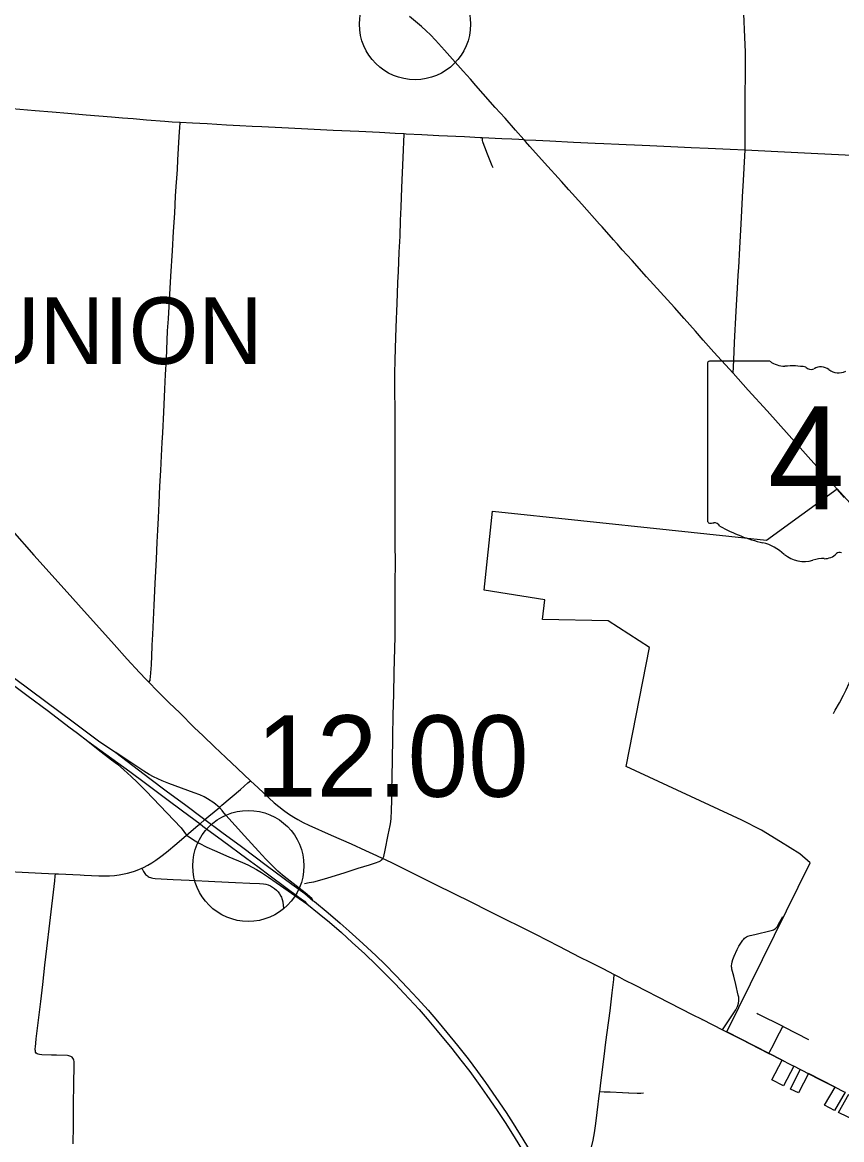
# Model space of a CAD drawing. Extents: x 1597222 to 1925846, y 496284 to 911751.
# Drawn here: x 1687501 to 1698562, y 561679 to 576766 of the extents above; entities that cross this region are included whole.
import ezdxf

# ---------------------------------------------------------------- set-up
doc = ezdxf.new("R2010")
doc.units = 0
for name, color, linetype in [('Default', 7, 'Continuous'), ('GM_X_City_Street', 7, 'Continuous'), ('GM_X_Corporation', 7, 'Continuous'), ('GM_X_County_Road', 7, 'Continuous'), ('GM_X_Interchange_Ramps', 7, 'Continuous'), ('GM_X_State_Route', 7, 'Continuous'), ('GM_X_State_Shield', 7, 'Continuous'), ('GM_X_Township_Road', 7, 'Continuous'), ('GM_X_Township_Text', 7, 'Continuous'), ('GM_X_US_Route', 7, 'Continuous')]:
    doc.layers.add(name, color=color, linetype=linetype)

msp = doc.modelspace()

# ---------------------------------------------------------------- linework, layer by layer
at = {"layer": 'Default'}
for centre in [(1692802, 576741), (1692802, 576741), (1690551, 565375), (1690551, 565375)]:
    msp.add_circle(centre, 750, dxfattribs=at)
at = {"layer": 'GM_X_City_Street'}
for points in [[(1698451, 567435), (1698474, 567479), (1698532, 567579), (1698587, 567680), (1698623, 567754), (1698665, 567843), (1698681, 567872), (1698690, 567886)], [(1696955, 563162), (1696971, 563187), (1696998, 563228), (1697042, 563297), (1697116, 563404), (1697133, 563432), (1697148, 563460), (1697154, 563475), (1697160, 563490), (1697168, 563521), (1697173, 563553), (1697174, 563569), (1697174, 563585), (1697172, 563601), (1697166, 563632), (1697132, 563775), (1697104, 563886), (1697086, 563949), (1697080, 563981), (1697078, 563998), (1697076, 564014), (1697076, 564031), (1697078, 564048), (1697084, 564080), (1697094, 564112), (1697112, 564158), (1697153, 564247), (1697175, 564291), (1697201, 564333), (1697229, 564374), (1697239, 564387), (1697251, 564399), (1697264, 564410), (1697279, 564418), (1697294, 564425), (1697326, 564436), (1697390, 564451), (1697612, 564502), (1697628, 564506), (1697643, 564512), (1697656, 564519), (1697669, 564528), (1697679, 564539), (1697689, 564552), (1697706, 564580), (1697767, 564693)], [(1697418, 563386), (1697432, 563379), (1697768, 563209)], [(1697579, 562843), (1697594, 562870), (1697641, 562958), (1697693, 563062), (1697753, 563180), (1697768, 563209)], [(1697768, 563209), (1697782, 563202), (1698116, 563032)], [(1697759, 562752), (1697772, 562746)], [(1697919, 562671), (1698004, 562626)], [(1698258, 562496), (1698332, 562459), (1698472, 562386)]]:
    msp.add_lwpolyline(points, dxfattribs=at)
at = {"layer": 'GM_X_Corporation'}
for points in [[(1698607, 562321), (1698463, 562073), (1698330, 562146), (1698473, 562389), (1698115, 562571), (1697979, 562309), (1697873, 562361), (1698003, 562628), (1697918, 562672), (1697778, 562407), (1697617, 562485), (1697758, 562754), (1697011, 563134), (1698135, 565417), (1697999, 565537), (1697736, 565700), (1697481, 565859), (1697213, 565994), (1695653, 566716), (1695966, 568325), (1695409, 568686), (1694523, 568702), (1694556, 568969), (1693735, 569099), (1693847, 570164), (1696232, 569913), (1697548, 569775), (1698502, 570468), (1698717, 570227)], [(1698985, 561819), (1698519, 562047), (1698660, 562293)]]:
    msp.add_lwpolyline(points, dxfattribs=at)
at = {"layer": 'GM_X_County_Road'}
for points in [[(1697257, 575044), (1697258, 575249), (1697261, 575610), (1697262, 576233), (1697262, 576364), (1697254, 576564), (1697242, 576881), (1697230, 577216), (1697211, 577527), (1697193, 577838), (1697178, 578083), (1697138, 578787), (1697122, 579066), (1697109, 579311), (1697093, 579590), (1697085, 579671), (1697078, 579720), (1697066, 579784), (1697045, 579863), (1696903, 580368), (1696829, 580637), (1696791, 580776)], [(1685437, 575768), (1685632, 575750), (1685975, 575719), (1686302, 575692), (1686629, 575665), (1686923, 575641), (1687364, 575602), (1687675, 575577), (1687903, 575557), (1688116, 575540), (1688361, 575519), (1688704, 575492), (1688851, 575479), (1688998, 575466), (1689178, 575450), (1689423, 575431), (1689521, 575425), (1689630, 575418)], [(1689630, 575418), (1689799, 575408), (1689996, 575399), (1690258, 575384), (1690438, 575374), (1690602, 575366), (1690733, 575359), (1691093, 575343), (1691355, 575329), (1691699, 575312), (1692043, 575295), (1692321, 575282), (1692534, 575269), (1692656, 575264)], [(1692369, 565474), (1692379, 565501), (1692399, 565587), (1692438, 565794), (1692467, 565922), (1692475, 565971), (1692479, 566020), (1692484, 566119), (1692487, 566267), (1692488, 566381), (1692494, 566595), (1692497, 566791), (1692503, 567119), (1692508, 567415), (1692515, 567694), (1692520, 567989), (1692529, 568317), (1692533, 568464), (1692536, 568563), (1692536, 568645), (1692536, 568989), (1692536, 569203), (1692537, 569465), (1692534, 569728), (1692535, 569974), (1692535, 570236), (1692533, 570450), (1692535, 570761), (1692534, 571057), (1692532, 571467), (1692532, 571615), (1692531, 571713), (1692530, 571819), (1692530, 571910), (1692530, 572025), (1692534, 572205), (1692543, 572517), (1692554, 572762), (1692558, 572861), (1692562, 572975), (1692566, 573107), (1692572, 573254), (1692579, 573401), (1692585, 573533), (1692590, 573664), (1692600, 573877), (1692608, 574090), (1692615, 574270), (1692626, 574532), (1692641, 574942), (1692656, 575256), (1692656, 575264)], [(1692656, 575264), (1692682, 575262), (1692895, 575252), (1693124, 575240), (1693468, 575224), (1693681, 575212), (1693709, 575211)], [(1693709, 575211), (1693976, 575200), (1694107, 575192), (1694205, 575187), (1694271, 575183)], [(1694271, 575183), (1694287, 575182), (1694433, 575175), (1694624, 575166), (1694942, 575150), (1695233, 575137)], [(1695233, 575137), (1695351, 575132), (1695554, 575122), (1695651, 575118)], [(1695651, 575118), (1695764, 575113), (1695973, 575104), (1696352, 575087), (1696531, 575077), (1696760, 575066), (1697056, 575053), (1697257, 575044)], [(1697229, 574489), (1697232, 574551), (1697246, 574796), (1697257, 575044)], [(1697257, 575044), (1697698, 575021), (1698239, 574996), (1698519, 574983), (1698697, 574974)], [(1697098, 572027), (1697107, 572204), (1697116, 572442), (1697138, 572868), (1697160, 573260), (1697166, 573354), (1697172, 573456), (1697187, 573717), (1697205, 574044), (1697229, 574489)], [(1685081, 572425), (1685120, 572384), (1685314, 572184), (1685392, 572100), (1685567, 571905), (1685731, 571722), (1685939, 571489), (1686070, 571343), (1686234, 571159), (1686694, 570647), (1686923, 570391), (1687142, 570147), (1687362, 569903), (1687656, 569573), (1687985, 569207), (1688182, 568988), (1688336, 568817), (1688543, 568584), (1688739, 568364), (1688914, 568169), (1689080, 567987), (1689171, 567892), (1689206, 567856)], [(1689206, 567856), (1689321, 567741), (1689484, 567579), (1689625, 567442), (1689822, 567245), (1689940, 567131), (1690094, 566984), (1690249, 566837), (1690405, 566692), (1690579, 566526)], [(1690160, 566165), (1690195, 566195), (1690445, 566408), (1690545, 566495), (1690579, 566526)], [(1690579, 566526), (1690682, 566429), (1690826, 566295), (1690899, 566229), (1690962, 566176), (1691027, 566126), (1691095, 566078), (1691164, 566034), (1691221, 566001), (1691294, 565962), (1691368, 565927), (1691668, 565792), (1691938, 565672), (1692132, 565584), (1692281, 565515), (1692369, 565474)], [(1689717, 565790), (1689871, 565919), (1689899, 565943), (1689966, 566001), (1690020, 566046), (1690160, 566165)], [(1689112, 565345), (1689135, 565355), (1689193, 565385), (1689249, 565418), (1689304, 565453), (1689370, 565501), (1689448, 565562), (1689586, 565678), (1689717, 565790)], [(1684630, 565427), (1684729, 565423), (1685008, 565409), (1685270, 565397), (1685565, 565383), (1685909, 565366), (1686171, 565356), (1686696, 565330), (1687056, 565313), (1687761, 565278), (1687950, 565269)], [(1688282, 565253), (1688334, 565251), (1688531, 565242), (1688613, 565240), (1688678, 565242), (1688743, 565247), (1688808, 565255), (1688873, 565266), (1688920, 565276), (1688968, 565289), (1689014, 565305), (1689075, 565328), (1689112, 565345)], [(1689112, 565345), (1689138, 565302), (1689155, 565274), (1689165, 565261), (1689176, 565250), (1689188, 565239), (1689201, 565230), (1689214, 565223), (1689229, 565217), (1689244, 565212), (1689260, 565208), (1689292, 565203), (1689374, 565199), (1689538, 565192), (1689752, 565183), (1690097, 565166), (1690376, 565153), (1690573, 565144), (1690704, 565138), (1690754, 565133), (1690786, 565127), (1690819, 565118), (1690849, 565105), (1690879, 565089), (1690906, 565070), (1690931, 565048), (1690954, 565024), (1690974, 564997), (1690991, 564968), (1690998, 564953), (1691004, 564937), (1691009, 564922), (1691017, 564889), (1691023, 564840), (1691025, 564807)], [(1692369, 565474), (1692400, 565460), (1692504, 565411), (1692872, 565228), (1693077, 565126), (1693563, 564885), (1693784, 564775), (1694048, 564643), (1694195, 564569), (1694430, 564452), (1694745, 564291)], [(1687950, 565269), (1687990, 565267), (1688282, 565253)], [(1694745, 564291), (1695029, 564145), (1695159, 564079)], [(1695159, 564079), (1695337, 563989), (1695492, 563907)], [(1695295, 562326), (1695310, 562445), (1695356, 562802), (1695380, 562997), (1695397, 563127), (1695435, 563418), (1695464, 563662), (1695485, 563841), (1695492, 563907)], [(1695492, 563907), (1695562, 563873), (1695626, 563839), (1695773, 563766), (1695921, 563690), (1696078, 563609), (1696544, 563370), (1696672, 563306), (1696676, 563303)], [(1696676, 563303), (1696681, 563301), (1696955, 563162)], [(1696955, 563162), (1697072, 563103), (1697203, 563035), (1697579, 562843)], [(1697579, 562843), (1697611, 562827), (1697713, 562775), (1697759, 562752)], [(1697772, 562746), (1697785, 562739), (1697835, 562713), (1697881, 562690), (1697905, 562677), (1697919, 562671)], [(1698004, 562626), (1698258, 562496)], [(1695047, 561154), (1695073, 561218), (1695107, 561311), (1695137, 561404), (1695160, 561482), (1695184, 561577), (1695205, 561673), (1695223, 561770), (1695241, 561899), (1695259, 562046), (1695292, 562306), (1695295, 562326)], [(1695690, 562305), (1695686, 562305), (1695602, 562309), (1695436, 562318), (1695357, 562321), (1695295, 562326)], [(1698472, 562386), (1698587, 562329), (1698608, 562319)], [(1695885, 562306), (1695852, 562302), (1695802, 562301), (1695690, 562305)]]:
    msp.add_lwpolyline(points, dxfattribs=at)
at = {"layer": 'GM_X_Interchange_Ramps'}
for points in [[(1688386, 567060), (1688523, 566949), (1688706, 566809), (1688784, 566748), (1688871, 566673), (1688969, 566584), (1689052, 566505), (1689166, 566387), (1689644, 565888), (1689717, 565790)], [(1690160, 566165), (1690085, 566227), (1689998, 566283), (1689954, 566306), (1689895, 566334), (1689819, 566364), (1689480, 566489), (1689388, 566524), (1689328, 566551), (1689269, 566579), (1689211, 566611), (1689142, 566654), (1688992, 566755), (1688764, 566907)], [(1691429, 564905), (1691408, 564936), (1691319, 565012), (1691075, 565199), (1691012, 565251), (1690950, 565305), (1690892, 565362), (1690788, 565467), (1690688, 565574), (1690501, 565780), (1690248, 566059), (1690206, 566109), (1690196, 566122), (1690160, 566165)], [(1689717, 565790), (1689832, 565712), (1689889, 565681), (1689991, 565630), (1690095, 565582), (1690290, 565499), (1690471, 565423), (1690545, 565390), (1690604, 565360), (1690660, 565328), (1690730, 565285), (1690824, 565221), (1691342, 564863)]]:
    msp.add_lwpolyline(points, dxfattribs=at)
at = {"layer": 'GM_X_State_Route'}
for points in [[(1694295, 575156), (1694277, 575176), (1694271, 575183), (1694158, 575311), (1694017, 575471), (1693886, 575618), (1693723, 575802), (1693624, 575912), (1693549, 575998), (1693450, 576109), (1693309, 576268), (1693200, 576391), (1693079, 576525), (1693011, 576596), (1692952, 576653), (1692891, 576708), (1692727, 576845)], [(1697098, 572027), (1696838, 572314), (1696694, 572475), (1696589, 572594), (1696434, 572768), (1696304, 572914), (1696116, 573123), (1695928, 573329), (1695732, 573549), (1695599, 573696), (1695536, 573769), (1695521, 573786), (1695480, 573831), (1695328, 574003), (1695294, 574039), (1695053, 574310), (1694879, 574505), (1694781, 574615), (1694551, 574870), (1694354, 575091), (1694295, 575156)], [(1698500, 570463), (1698109, 570898), (1698001, 571019), (1697555, 571520), (1697301, 571800), (1697098, 572027)], [(1698602, 570350), (1698500, 570463)]]:
    msp.add_lwpolyline(points, dxfattribs=at)
at = {"layer": 'GM_X_State_Shield'}
for p, q in [((1696752, 572154), (1696752, 570041)), ((1697594, 572191), (1696779, 572191))]:
    msp.add_line(p, q, dxfattribs=at)
for centre, radius, start, end in [((1696783, 572159), 32.3, 98.1301, 188.1301), ((1697789, 572436), 313, 231.6195, 271.1119), ((1697892, 571004), 1123, 80.4867, 94.9883), ((1698147, 572170), 90.3, 219.7921, 297.1024), ((1698280, 571925), 188, 54.4667, 119.1411), ((1698522, 572260), 226, 233.8562, 294.8282), ((1696784, 570036), 32.5, 171.9584, 258.3066), ((1696789, 570253), 248, 267.339, 280.6039), ((1696839, 569919), 89.5, 29.7484, 93.2717), ((1697970, 571818), 2132, 240.4129, 257.1985), ((1697334, 569092), 667, 47.1842, 75.836), ((1698056, 569909), 423, 230.7004, 286.2918), ((1698331, 569750), 226, 268.777, 315.5493), ((1698535, 569546), 63.5, 65.7517, 132.6484), ((1698300, 569178), 348, 85.6951, 111.2099)]:
    msp.add_arc(centre, radius, start, end, dxfattribs=at)
at = {"layer": 'GM_X_Township_Road'}
for points in [[(1689438, 572077), (1689446, 572222), (1689456, 572468), (1689462, 572599), (1689472, 572763), (1689487, 573009), (1689505, 573337), (1689526, 573681), (1689543, 573943), (1689557, 574189), (1689570, 574418), (1689577, 574549), (1689585, 574664), (1689593, 574778), (1689601, 574909), (1689619, 575221), (1689627, 575352), (1689630, 575406), (1689630, 575418)], [(1693855, 574800), (1693842, 574830), (1693782, 574986), (1693746, 575079), (1693724, 575141), (1693719, 575155), (1693715, 575173), (1693714, 575181), (1693712, 575189), (1693709, 575211)], [(1689255, 568355), (1689263, 568501), (1689272, 568697), (1689282, 568894), (1689295, 569189), (1689310, 569517), (1689320, 569747), (1689330, 569911), (1689337, 570075), (1689347, 570273), (1689358, 570501), (1689370, 570714), (1689379, 570911), (1689390, 571091), (1689396, 571222), (1689410, 571501), (1689426, 571812), (1689435, 572009), (1689438, 572077)], [(1689206, 567856), (1689224, 567878), (1689228, 567893), (1689231, 567927), (1689242, 568091), (1689254, 568337), (1689255, 568355)], [(1691309, 565139), (1691373, 565150), (1691438, 565162), (1691517, 565182), (1691627, 565214), (1691846, 565283), (1692033, 565343), (1692189, 565392), (1692283, 565422), (1692306, 565429), (1692318, 565433), (1692329, 565439), (1692338, 565444), (1692346, 565451), (1692354, 565458), (1692369, 565474)], [(1688188, 561621), (1688190, 561866), (1688193, 562194), (1688195, 562391), (1688199, 562719), (1688198, 562735), (1688195, 562751), (1688190, 562767), (1688182, 562781), (1688171, 562792), (1688157, 562801), (1688142, 562807), (1688126, 562811), (1688109, 562813), (1687962, 562819), (1687896, 562821), (1687765, 562826), (1687733, 562828), (1687716, 562831), (1687702, 562837), (1687689, 562848), (1687680, 562861), (1687676, 562877), (1687674, 562893), (1687674, 562910), (1687676, 562926), (1687689, 563040), (1687728, 563366), (1687749, 563545), (1687776, 563772), (1687806, 564033), (1687832, 564261), (1687871, 564603), (1687937, 565173), (1687945, 565238), (1687950, 565269)]]:
    msp.add_lwpolyline(points, dxfattribs=at)
at = {"layer": 'GM_X_US_Route'}
for points in [[(1686949, 568240), (1687818, 567594), (1688187, 567321), (1688529, 567066), (1688764, 566907), (1689220, 566556), (1689443, 566389), (1689706, 566194), (1689930, 566027), (1689966, 566001), (1690194, 565833), (1690457, 565637), (1690812, 565372), (1691141, 565128), (1691313, 565002), (1691429, 564905), (1691444, 564893), (1691629, 564741), (1691792, 564604), (1691915, 564495), (1692096, 564329), (1692276, 564161), (1692394, 564047), (1692543, 563896), (1692702, 563730), (1692836, 563586), (1692978, 563427), (1693107, 563279), (1693233, 563127), (1693377, 562949), (1693519, 562768), (1693647, 562598), (1693753, 562452), (1693893, 562250), (1694031, 562047), (1694129, 561895), (1694258, 561686), (1694368, 561503)], [(1687101, 568021), (1687562, 567679), (1687852, 567463), (1688126, 567254), (1688245, 567167), (1688386, 567060), (1688950, 566648), (1689161, 566491), (1689451, 566277), (1689662, 566121), (1689899, 565943), (1689937, 565914), (1690201, 565719), (1690530, 565475), (1690678, 565366)], [(1690678, 565366), (1690847, 565242), (1691233, 564953), (1691308, 564899), (1691342, 564863)], [(1691342, 564863), (1691508, 564729), (1691647, 564614), (1691808, 564474), (1691955, 564343), (1692123, 564187), (1692278, 564040), (1692418, 563901), (1692533, 563784), (1692656, 563652), (1692856, 563435), (1692964, 563312), (1693102, 563149), (1693300, 562908), (1693422, 562754), (1693541, 562597), (1693676, 562411), (1693771, 562277), (1693909, 562073), (1694017, 561909), (1694140, 561715), (1694251, 561533)]]:
    msp.add_lwpolyline(points, dxfattribs=at)

# ---------------------------------------------------------------- texts
at = {"layer": 'Default'}
msp.add_text('12.00', height=1100, dxfattribs=at).set_placement((1690656, 566309))
at = {"layer": 'GM_X_State_Shield'}
msp.add_text('41', height=1392.2, dxfattribs=at).set_placement((1697566, 570190))
at = {"layer": 'GM_X_Township_Text'}
msp.add_text('UNION', height=900, rotation=0, dxfattribs=at).set_placement((1686866, 572153))

doc.saveas('drawing.dxf')
